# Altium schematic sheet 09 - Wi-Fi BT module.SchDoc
size B; CompanyName: Microchip Technology Inc.; Organization: Microchip Technology; Address1: 2355 West Chandler Blvd.; Address2: Chandler, AZ  85224; Address4: USA; DocumentNumber: 9; SheetNumber: 9; SheetTotal: 13; SheetTitle: Wi-Fi BT
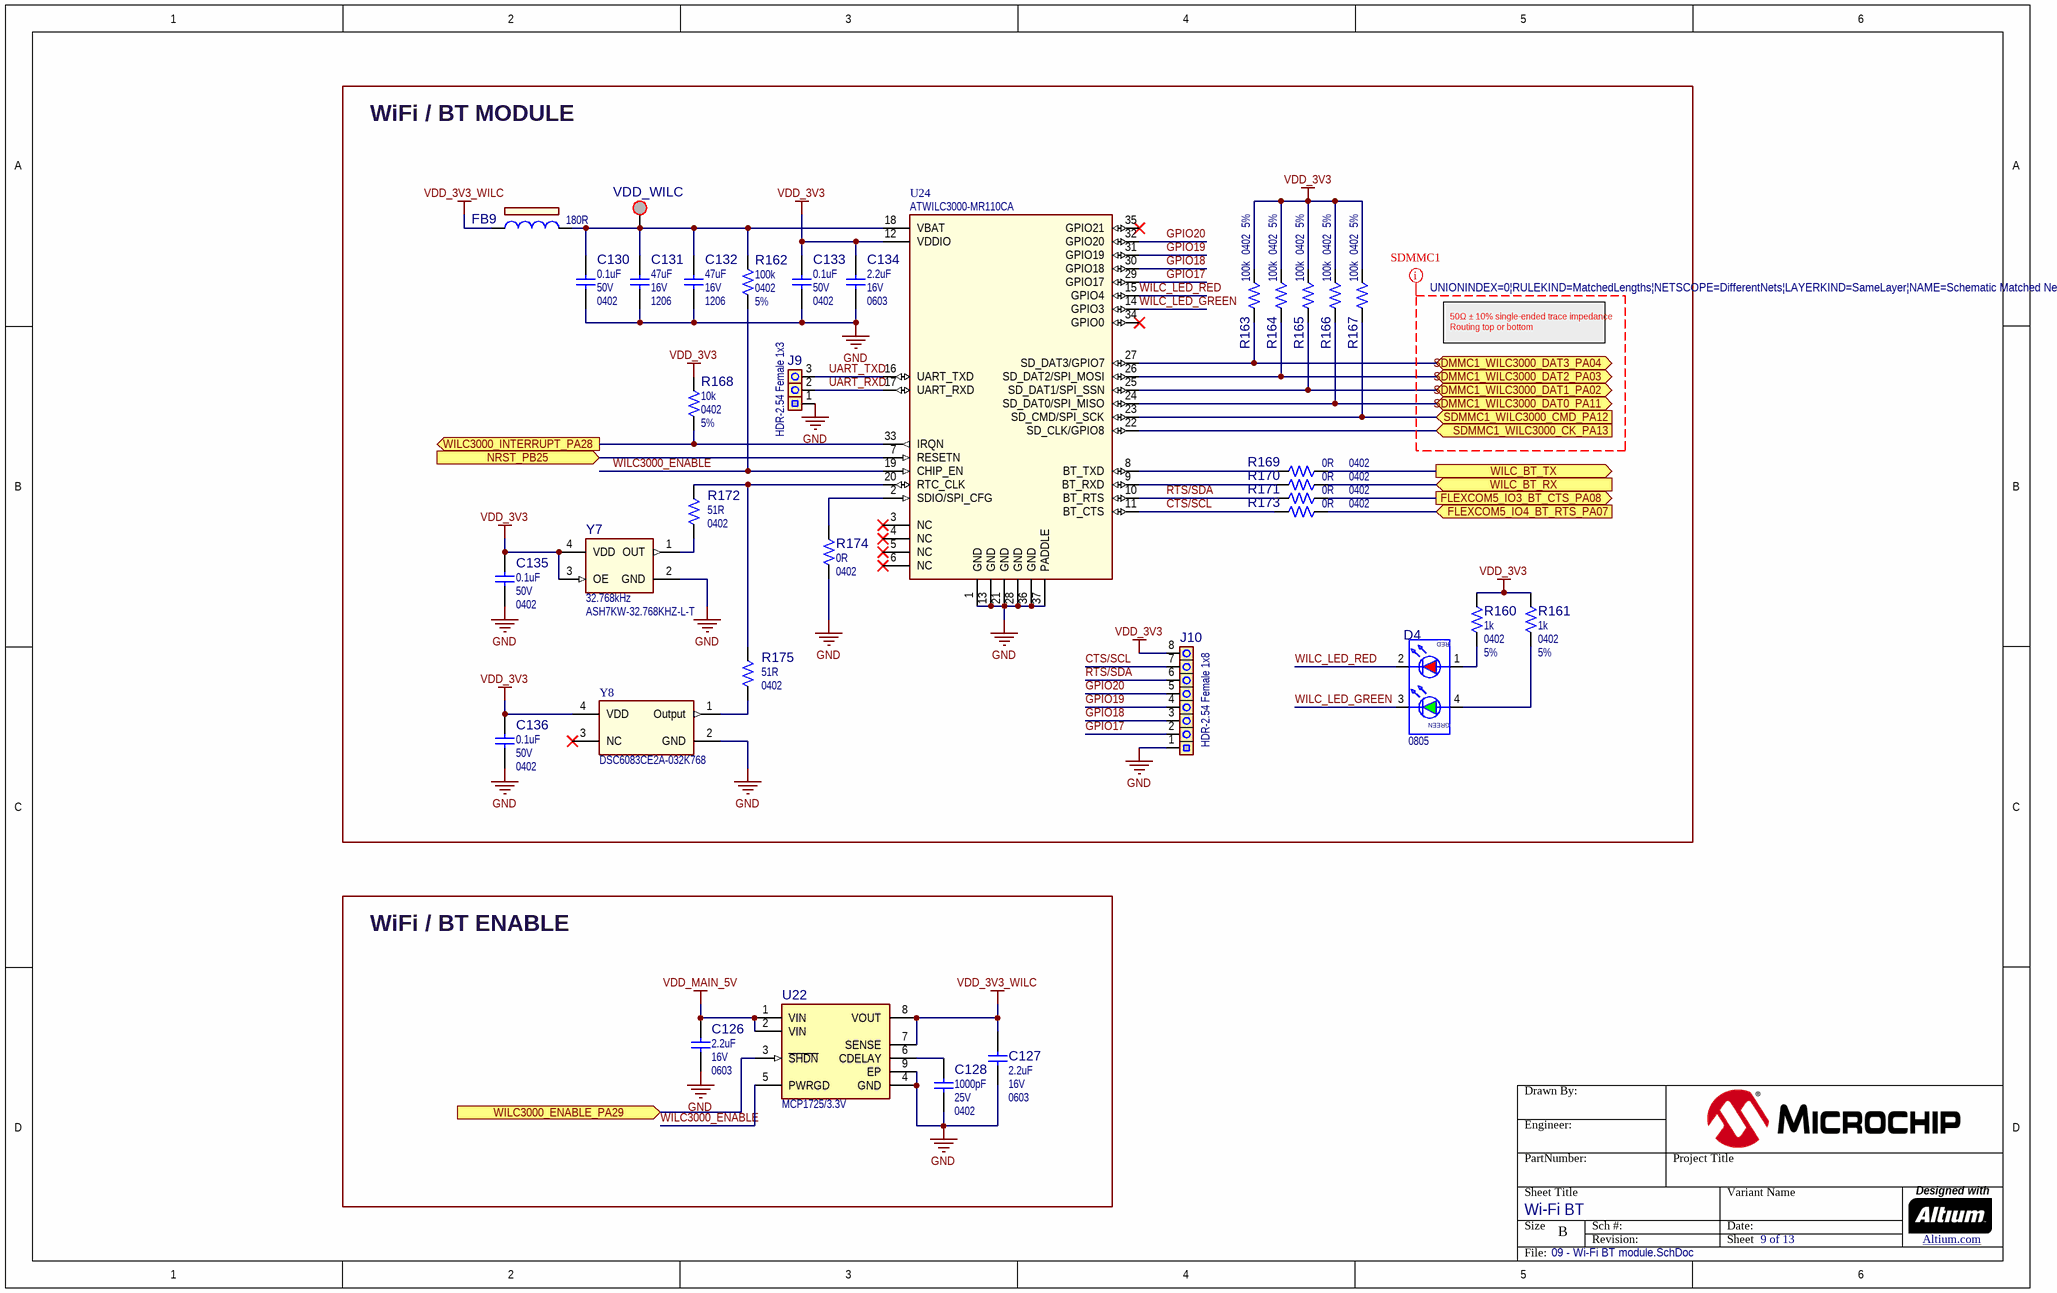
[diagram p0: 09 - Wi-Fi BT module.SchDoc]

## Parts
?  (no value)  (graphical)
C126  value 2.2uF  Voltage: 16V  Package: 0603  [CAP_C_0603]  (hidden comment: Capacitor NP)
C127  value 2.2uF  Voltage: 16V  Package: 0603  [CAP_C_0603]  (hidden comment: Capacitor NP)
C128  value 1000pF  Voltage: 25V  Package: 0402  [CAP_C_0402]  (hidden comment: Capacitor NP)
C130  value 0.1uF  Voltage: 50V  Package: 0402  [CAP_C_0402]  (hidden comment: Capacitor NP)
C131  value 47uF  Voltage: 16V  Package: 1206  [CAP_C_1206]  (hidden comment: Capacitor NP)
C132  value 47uF  Voltage: 16V  Package: 1206  [CAP_C_1206]  (hidden comment: Capacitor NP)
C133  value 0.1uF  Voltage: 50V  Package: 0402  [CAP_C_0402]  (hidden comment: Capacitor NP)
C134  value 2.2uF  Voltage: 16V  Package: 0603  [CAP_C_0603]  (hidden comment: Capacitor NP)
C135  value 0.1uF  Voltage: 50V  Package: 0402  [CAP_C_0402]  (hidden comment: Capacitor NP)
C136  value 0.1uF  Voltage: 50V  Package: 0402  [CAP_C_0402]  (hidden comment: Capacitor NP)
D4  Package: 0805  [LED_DUAL_SMD_2x1.25mm]  (hidden comment: LED DUAL 4 pin)
FB9  value 180R  [IND_C_0603]  (hidden comment: Ferrite Bead)
J9  value HDR-2.54 Female 1x3  [HDR_F_2.54_1x3]  (hidden comment: Header 1x3)
J10  value HDR-2.54 Female 1x8  [HDR_F_2.54_1X8]  (hidden comment: Header 1x8)
R160  value 1k  Package: 0402  Tolerance: 5%  [RES_C_0402]  (hidden comment: Resistor)
R161  value 1k  Package: 0402  Tolerance: 5%  [RES_C_0402]  (hidden comment: Resistor)
R162  value 100k  Package: 0402  Tolerance: 5%  [RES_C_0402]  (hidden comment: Resistor)
R163  value 100k  Package: 0402  Tolerance: 5%  [RES_C_0402]  (hidden comment: Resistor)
R164  value 100k  Package: 0402  Tolerance: 5%  [RES_C_0402]  (hidden comment: Resistor)
R165  value 100k  Package: 0402  Tolerance: 5%  [RES_C_0402]  (hidden comment: Resistor)
R166  value 100k  Package: 0402  Tolerance: 5%  [RES_C_0402]  (hidden comment: Resistor)
R167  value 100k  Package: 0402  Tolerance: 5%  [RES_C_0402]  (hidden comment: Resistor)
R168  value 10k  Package: 0402  Tolerance: 5%  [RES_C_0402]  (hidden comment: Resistor)
R169  value 0R  Package: 0402  [RES_C_0402]  (hidden comment: Resistor)
R170  value 0R  Package: 0402  [RES_C_0402]  (hidden comment: Resistor)
R171  value 0R  Package: 0402  [RES_C_0402]  (hidden comment: Resistor)
R172  value 51R  Package: 0402  [RES_C_0402]  (hidden comment: Resistor)
R173  value 0R  Package: 0402  [RES_C_0402]  (hidden comment: Resistor)
R174  value 0R  Package: 0402  [RES_C_0402]  (hidden comment: Resistor)
R175  value 51R  Package: 0402  [RES_C_0402]  (hidden comment: Resistor)
U22  value MCP1725/3.3V  [DFN-8_2x3]  (hidden comment: MCP172X FIX DFN-8)
U24  value ATWILC3000-MR110CA  [MODULE ATWILC3000-MR110CA]  (hidden comment: MODULE ATWILC3000-MR110CA)
VDD_WILC  SMD Test Point  [TP_1x1_SMD]  (value not drawn)  (no BOM)
Y7  value 32.768kHz  Manufacturer Part Number 1: ASH7KW-32.768KHZ-L-T  [OSCILLATOR_ASH7KW_L3.2W1.5H1]  (hidden comment: OSCILLATOR ASH7KW)
Y8  Manufacturer Part Number 1: DSC6083CE2A-032K768  [OSCILLATOR_DSC1001_L3.2W2.5H0.85]  (hidden comment: OSC_DSC6083CE2A_3225)

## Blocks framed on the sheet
WiFi / BT MODULE: C130-C136 D4 FB9 J9 J10 R160-R175 U24 VDD_WILC Y7 Y8
WiFi / BT ENABLE: C126-C128 U22

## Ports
FLEXCOM5_IO3_BT_CTS_PA08 (out), FLEXCOM5_IO4_BT_RTS_PA07 (in), NRST_PB25 (in), SDMMC1_WILC3000_CK_PA13 (in), SDMMC1_WILC3000_CMD_PA12 (in), SDMMC1_WILC3000_DAT0_PA11 (bidir), SDMMC1_WILC3000_DAT1_PA02 (bidir), SDMMC1_WILC3000_DAT2_PA03 (bidir), SDMMC1_WILC3000_DAT3_PA04 (bidir), WILC3000_ENABLE_PA29 (in), WILC3000_INTERRUPT_PA28 (out), WILC_BT_RX (in), WILC_BT_TX (out)

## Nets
GND: C126.2 C127.1 C128.1 C130.2 C131.2 C132.2 C133.2 C134.1 C135.2 C136.2 J9.1 J10.1 R174.2 U22.4(GND) U22.9(EP) U24.1(GND) U24.13(GND) U24.21(GND) U24.28(GND) U24.36(GND) U24.37(PADDLE) Y7.2(GND) Y8.2(GND)
VDD_3V3: C133.1 C134.2 C135.1 C136.1 J10.8 R160.2 R161.2 R163.2 R164.2 R165.2 R166.2 R167.2 R168.2 U24.12(VDDIO) Y7.3(OE) Y7.4(VDD) Y8.4(VDD)
VDD_3V3_WILC: C127.2 FB9.1 U22.7(SENSE) U22.8(VOUT)
VDD_MAIN_5V: C126.1 U22.1(VIN) U22.2(VIN)
CTS/SCL: J10.7 R173.1 U24.11(BT_CTS)
FLEXCOM5_IO3_BT_CTS_PA08: R171.2 ; port FLEXCOM5_IO3_BT_CTS_PA08
FLEXCOM5_IO4_BT_RTS_PA07: R173.2 ; port FLEXCOM5_IO4_BT_RTS_PA07
GPIO17: J10.2 U24.29(GPIO17)
GPIO18: J10.3 U24.30(GPIO18)
GPIO19: J10.4 U24.31(GPIO19)
GPIO20: J10.5 U24.32(GPIO20)
NRST_PB25: U24.7(RESETN) ; port NRST_PB25
RTS/SDA: J10.6 R171.1 U24.10(BT_RTS)
SDMMC1_WILC3000_CK_PA13: U24.22(SD_CLK/GPIO8) ; port SDMMC1_WILC3000_CK_PA13
SDMMC1_WILC3000_CMD_PA12: R167.1 U24.23(SD_CMD/SPI_SCK) ; port SDMMC1_WILC3000_CMD_PA12
SDMMC1_WILC3000_DAT0_PA11: R166.1 U24.24(SD_DAT0/SPI_MISO) ; port SDMMC1_WILC3000_DAT0_PA11
SDMMC1_WILC3000_DAT1_PA02: R165.1 U24.25(SD_DAT1/SPI_SSN) ; port SDMMC1_WILC3000_DAT1_PA02
SDMMC1_WILC3000_DAT2_PA03: R164.1 U24.26(SD_DAT2/SPI_MOSI) ; port SDMMC1_WILC3000_DAT2_PA03
SDMMC1_WILC3000_DAT3_PA04: R163.1 U24.27(SD_DAT3/GPIO7) ; port SDMMC1_WILC3000_DAT3_PA04
UART_RXD: J9.2 U24.17(UART_RXD)
UART_TXD: J9.3 U24.16(UART_TXD)
WILC3000_ENABLE: R162.1 U22.5(PWRGD) U24.19(CHIP_EN)
WILC3000_ENABLE_PA29: U22.3(~{SHDN}) ; port WILC3000_ENABLE_PA29
WILC3000_INTERRUPT_PA28: R168.1 U24.33(IRQN) ; port WILC3000_INTERRUPT_PA28
WILC_BT_RX: R170.2 ; port WILC_BT_RX
WILC_BT_TX: R169.2 ; port WILC_BT_TX
WILC_LED_GREEN: D4.3(K2) U24.14(GPIO3)
WILC_LED_RED: D4.2(K1) U24.15(GPIO4)
NetC128_2: C128.2 U22.6(CDELAY)
NetC130_1: C130.1 C131.1 C132.1 FB9.2 R162.2 U24.18(VBAT) VDD_WILC.1
NetD4_1: D4.1(A1) R160.1
NetD4_4: D4.4(A2) R161.1
NetR169_1: R169.1 U24.8(BT_TXD)
NetR170_1: R170.1 U24.9(BT_RXD)
NetR172_1: R172.1 R175.1 U24.20(RTC_CLK)
NetR172_2: R172.2 Y7.1(OUT)
NetR174_1: R174.1 U24.2(SDIO/SPI_CFG)
NetR175_2: R175.2 Y8.1(Output)

Not connected (* = marked no-connect by the designer): U24 3(NC)* 4(NC)* 5(NC)* 6(NC)* 34(GPIO0)* 35(GPIO21)*; Y8 3(NC)*

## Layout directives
net class SDMMC-1; rule Matched Net Lengths [Tolerance = 0.25mm]: (no net found under the mark)

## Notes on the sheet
- 50Ω ± 10% single-ended trace impedance
  Routing top or bottom

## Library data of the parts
? = Title Block B
C126 C127 C134 = CAP0597: Capacitor; Manufacturer 1: TDK; Manufacturer Part Number 1: C1608X5R1C225K; Description_: CAP CER 2.2uF 16V 10% X5R SMD 0603; Dev Tools Status: Production; Tolerance: 10%; Temperature Coeffcient: X5R; Type: Ceramic; Populated: Yes
C128 = CAP0566: Capacitor; Manufacturer 1: TDK; Manufacturer Part Number 1: C1005C0G1E102J; Description_: CAP CER 1000pF 25V 5% C0G SMD 0402; Dev Tools Status: Production; Tolerance: 5%; Temperature Coeffcient: C0G; Type: Ceramic; Populated: Yes
C130 C133 C136 = CAP1463: Capacitor; Manufacturer 1: TDK Corporation; Manufacturer Part Number 1: C1005X7R1H104K050BB; Description_: CAP CER 0.1uF 50V 10% X7R SMD 0402; Dev Tools Status: Production; Tolerance: 10%; Temperature Coeffcient: X7R; Type: Ceramic; Owner: Jamus Griego; Populated: YES
C131 = CAP1331: Capacitor; Manufacturer 1: TDK Corporation; Manufacturer Part Number 1: C3216X5R1C476M160AB; Description_: CAP CER 47uF 16V 20% X5R SMD 1206; Dev Tools Status: Production; Tolerance: 20%; Temperature Coeffcient: X5R; Type: Ceramic; Owner: Bogdan Popescu; Populated: YES
C132 = CAP1331: Capacitor; Manufacturer 1: TDK Corporation; Manufacturer Part Number 1: C3216X5R1C476M160AB; Description_: CAP CER 47uF 16V 20% X5R SMD 1206; Dev Tools Status: Production; Tolerance: 20%; Temperature Coeffcient: X5R; Type: Ceramic; Owner: Bogdan Popescu; Populated: DNP
C135 = CAP1463: Capacitor; Manufacturer 1: TDK Corporation; Manufacturer Part Number 1: C1005X7R1H104K050BB; Description_: CAP CER 0.1uF 50V 10% X7R SMD 0402; Dev Tools Status: Production; Tolerance: 10%; Temperature Coeffcient: X7R; Type: Ceramic; Owner: Jamus Griego; Populated: DNP
D4 = DIODE1110: LED; Manufacturer 1: Kingbright Corp; Manufacturer Part Number 1: APHBM2012SURKCGKC; Value: RED, GREEN; Description_: DIO LED BI RED, GREEN 1.95V, 2.1V 30mA 0805; Dev Tools Status: Production; Type: LED Bicolor; Forward Current: 30mA; Power: 75mW; Reverse Current: 10uA; Owner: Bogdan P (M91398); Populated: Yes
FB9 = IND1453: FERRITE 180R 1.5A SMD 0603; Manufacturer 1: Murata Electronics North America; Manufacturer Part Number 1: BLM18PG181SN1D; Dev Tools Status: Production; Owner: Dragos Danaila; DCR: 0.09R; Test Frequency: 100MHz; Populated: YES
J9 = CON1425: Manufacturer 1: TE Connectivity AMP Connectors; Manufacturer Part Number 1: 5-534237-1; Description_: CON HDR-2.54 Female 1x3 Gold 8.64MH TH VERT; Dev Tools Status: Production; Owner: Md Khan; Populated: DNP
J10 = CON1363: CON HDR-2.54 Female 1x8 Gold TH; Manufacturer 1: Sullins Connector Solutions; Manufacturer Part Number 1: PPPC081LFBN-RC; Dev Tools Status: Production; Owner: Jamus Griego; Populated: DNP
R160 R161 = RSMT0316: Manufacturer 1: Panasonic; Manufacturer Part Number 1: ERJ-2GEJ102X; Description_: RES TKF 1k 5% 1/16W SMD 0402; Dev Tools Status: Production; Voltage: 50V; Temperature Coeffcient: 200ppm/C; Power: 1/16W; Owner: Tad Ahlvers; Populated: YES
R162 = RES2196: Manufacturer 1: Yageo; Manufacturer Part Number 1: RC0402JR-07100KL; Description_: RES TKF 100k 5% 1/16W SMD 0402; Dev Tools Status: Design; Temperature Coeffcient: 100ppm/C; Power: 1/16W; Owner: Ilie Galan; Populated: YES
R163-R167 = RES2196: Manufacturer 1: Yageo; Manufacturer Part Number 1: RC0402JR-07100KL; Description_: RES TKF 100k 5% 1/16W SMD 0402; Dev Tools Status: Design; Temperature Coeffcient: 100ppm/C; Power: 1/16W; Owner: Ilie Galan; Populated: DNP
R168 = RSMT0439: Manufacturer 1: Vishay; Manufacturer Part Number 1: CRCW040210K0JNED; Description_: RES TKF 10k 5% 1/16W SMD 0402; Dev Tools Status: Production; Voltage: 50V; Temperature Coeffcient: 100ppm/C; Power: 1/16W; Populated: Yes
R169-R171 R173 R174 = RSMT1040: Manufacturer 1: Yageo; Manufacturer Part Number 1: RC0402JR-070RL; Description_: RES TKF 0R 1/16W SMD 0402; Dev Tools Status: Production; Power: 1/16W; Owner: Sompoch Loboonlert; Populated: Yes
R172 = RSMT1243: Manufacturer 1: Yageo; Manufacturer Part Number 1: RC0402FR-0751RL; Tolerance: 1%; Description_: RES TKF 51R 1% 1/16W SMD 0402; Dev Tools Status: Design; Voltage: 100V; Temperature Coeffcient: 100ppm/C; Current: 1A; Power: 1/16W; Owner: Ciprian Abramov; Populated: DNP
R175 = RSMT1243: Manufacturer 1: Yageo; Manufacturer Part Number 1: RC0402FR-0751RL; Tolerance: 1%; Description_: RES TKF 51R 1% 1/16W SMD 0402; Dev Tools Status: Design; Voltage: 100V; Temperature Coeffcient: 100ppm/C; Current: 1A; Power: 1/16W; Owner: Ciprian Abramov; Populated: YES
U22 = MIC2599: LDO; Manufacturer 1: Microchip; Manufacturer Part Number 1: MCP1725T-3302E/MC; Description_: MCHP ANALOG LDO 3.3V MCP1725T-3302E/MC DFN-8; MAPS Description: 500MA, LOW VOLTAGE LDO; Dev Tools Status: Production; MPC: GEAH1YB3XA33; LeadContent: Pb-FREE; PackingMedia: T/R; Stage: REL; LeadCount: 8; PackageWidth: 2x3x0.9mm; ForceMinOrderQtyMult: True; MinOrderQty: 1; TempRange: -40C to +125C; tblDeviceFamilyID: 1781; Populated: Yes
U24 = MIC7405: Manufacturer 1: Microchip Technology; Description_: MCHP RF WI-FI 802.11b/g/n ATWILC3000-MR110CA; MAPS Description: SmartConnect WILC3000-MR110CA Module; Dev Tools Status: Design; Owner: Ilie Galan; tblDeviceFamilyID: 11256; FrequencyRange: 2.412-2.472 MHz; MaxSpeedMHz: 0; PowerRX: 84mA (802.11n MCS7); PowerTX: 253mA (802.11n MCS7); Sleep: 1.25uA; Populated: YES
VDD_WILC = TEST-POINT: Test Point pad 1.00mm
Y7 = OSC1187: Manufacturer 1: Abracon LLC; Description_: OSCILLATOR 32.768KHZ 1.2V ~ 5.5V SMD DFN-4; Dev Tools Status: Design; Owner: Ilie Galan; Voltage: 1.2-5.5V; Tolerance: 20ppm; Supply Current: 1.8uA; Populated: DNP
Y8 = MIC7476: Manufacturer 1: Microchip Technology; Description_: MCHP CLOCK OSCILLATOR SINGLE 32.768Hz DSC6083CE2A-032K768 SMD DFN-4; Dev Tools Status: Production; Value: 32.768Hz; Owner: Dragos Danaila; Populated: YES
